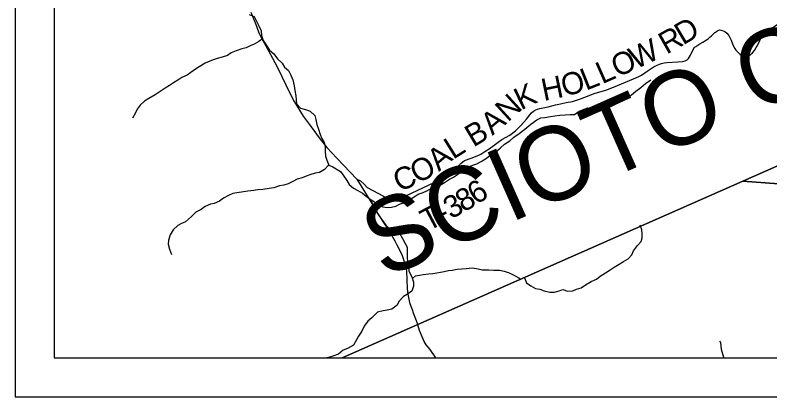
# Model space of a CAD drawing. Extents: x 0 to 44, y -23.8 to 22.
# Drawn here: x 2 to 3.933, y 14 to 14.979 of the extents above; entities that cross this region are included whole.
import ezdxf

# ---------------------------------------------------------------- set-up
doc = ezdxf.new("R2010")
doc.units = 0
for name, color, linetype in [('Default', 7, 'Continuous'), ('GM_X_County_Road', 7, 'Continuous'), ('GM_X_County_Text', 7, 'Continuous'), ('GM_X_Minor_River', 7, 'Continuous'), ('GM_X_Township_Road', 7, 'Continuous'), ('GM_X_Township_Road_Text', 7, 'Continuous'), ('SH_Cut_Line', 7, 'Continuous'), ('SH_Data', 7, 'Continuous')]:
    doc.layers.add(name, color=color, linetype=linetype)

msp = doc.modelspace()

# ---------------------------------------------------------------- linework, layer by layer
at = {"layer": 'Default'}
for points in [[(2.3497, 20.9), (2.1, 20.9), (2.1, 14.1), (2.838, 14.1), (3.0317, 14.1856), (3.8639, 14.5533), (4.3443, 14.7655), (4.4538, 14.8144), (4.856, 14.9939), (4.5387, 15.7097), (4.3476, 16.1408), (4.1422, 16.6361), (4.026, 16.9163), (3.7907, 17.4383), (3.763, 17.5087), (3.455, 18.29), (3.1789, 18.9421), (3.1321, 19.0527), (3.0496, 19.2474), (3.0092, 19.3427), (2.8013, 19.8369), (2.472, 20.6113)], [(2.838, 14.1), (7.2659, 14.1), (7.2787, 14.3616), (7.2065, 14.3659), (6.267, 14.4223), (4.4919, 14.5227), (4.3437, 14.5311), (4.2071, 14.5278), (3.8639, 14.5533), (3.0317, 14.1856)]]:
    msp.add_lwpolyline(points, close=True, dxfattribs=at)
msp.add_lwpolyline([(4.1422, 16.6361), (4.3476, 16.1408), (4.5387, 15.7097), (4.856, 14.9939), (4.4538, 14.8144), (4.3443, 14.7655), (3.8639, 14.5533), (4.2071, 14.5278), (4.3437, 14.5311), (4.4919, 14.5227), (6.267, 14.4223), (7.2065, 14.3659), (7.2787, 14.3616), (7.5613, 14.343)], dxfattribs=at)
at = {"layer": 'GM_X_County_Road'}
for points in [[(2.6042, 14.9868), (2.6157, 14.9579), (2.6238, 14.9364), (2.6307, 14.9214), (2.6424, 14.9001), (2.6717, 14.8463), (2.683, 14.8214), (2.7036, 14.7786), (2.7152, 14.7578), (2.738, 14.72), (2.7558, 14.6961), (2.7813, 14.6611), (2.7987, 14.6393), (2.8239, 14.612), (2.8751, 14.5584), (2.9086, 14.5045), (2.9313, 14.4671), (2.9596, 14.4222), (2.9725, 14.4), (2.9782, 14.3901), (2.9872, 14.3721), (2.9917, 14.3624), (2.9949, 14.3523), (2.9978, 14.3432), (3.0006, 14.3327), (3.0022, 14.3225), (3.0046, 14.2781), (3.0064, 14.2639), (3.0085, 14.2506), (3.0107, 14.2423), (3.0139, 14.2324), (3.0168, 14.2245), (3.02, 14.216), (3.032, 14.1851)], [(3.0774, 14.1), (3.0635, 14.1218), (3.0528, 14.1338), (3.0476, 14.142), (3.0429, 14.1537), (3.0361, 14.17), (3.032, 14.1851)]]:
    msp.add_lwpolyline(points, dxfattribs=at)
at = {"layer": 'GM_X_Minor_River'}
for points in [[(2.5996, 14.981), (2.612, 14.9756), (2.6191, 14.9623), (2.624, 14.952), (2.63, 14.9391), (2.631, 14.9273), (2.6355, 14.914), (2.6422, 14.9037), (2.6516, 14.8896), (2.6632, 14.8797), (2.6722, 14.8667), (2.6839, 14.8561), (2.6903, 14.8458), (2.7004, 14.837), (2.7064, 14.8256), (2.7112, 14.8134), (2.7149, 14.7982), (2.7167, 14.7861), (2.7189, 14.7724), (2.72, 14.7618), (2.7211, 14.7515), (2.7312, 14.7408), (2.744, 14.7374), (2.7557, 14.7327), (2.7674, 14.7217), (2.7707, 14.7114), (2.7733, 14.6989), (2.777, 14.6863), (2.7818, 14.6734), (2.7859, 14.6628), (2.7916, 14.6529), (2.7945, 14.6403), (2.7944, 14.6305), (2.7951, 14.6172), (2.7985, 14.6073), (2.804, 14.594), (2.8139, 14.5898), (2.8334, 14.5783), (2.8402, 14.5687), (2.8496, 14.5554), (2.8559, 14.5451), (2.8668, 14.5352), (2.8781, 14.5291), (2.8902, 14.5222), (2.9034, 14.5111), (2.9166, 14.503), (2.9282, 14.495), (2.9422, 14.4873), (2.9543, 14.4854), (2.9641, 14.4865), (2.9751, 14.489), (2.9846, 14.4943), (2.9971, 14.4988), (3.0092, 14.5055), (3.0225, 14.5134), (3.0324, 14.5198), (3.0449, 14.5243)], [(2.6341, 14.9181), (2.6245, 14.9118), (2.612, 14.905), (2.6025, 14.9005), (2.5915, 14.8957), (2.5805, 14.8927), (2.5665, 14.8875), (2.5536, 14.8823), (2.5441, 14.8759), (2.5301, 14.8714), (2.5176, 14.8677), (2.5073, 14.8643), (2.4967, 14.8602), (2.4865, 14.8561), (2.4717, 14.8463), (2.4622, 14.8407), (2.45, 14.8317), (2.4405, 14.8249), (2.4269, 14.8193), (2.417, 14.8121), (2.4056, 14.8058), (2.3958, 14.7986), (2.384, 14.7915), (2.3718, 14.7832), (2.3586, 14.7746), (2.3426, 14.7652), (2.3312, 14.7584), (2.3202, 14.7482), (2.3126, 14.7384), (2.308, 14.7282), (2.3011, 14.715)], [(3.0449, 14.5243), (3.0544, 14.5288), (3.0642, 14.5333), (3.0741, 14.5374), (3.0873, 14.5426), (3.1002, 14.5497), (3.1124, 14.5584), (3.1226, 14.564), (3.1329, 14.5708), (3.1428, 14.5779), (3.1606, 14.5896), (3.1724, 14.5941), (3.183, 14.5982), (3.194, 14.6038), (3.2073, 14.6124), (3.2172, 14.6203), (3.2304, 14.6278), (3.2434, 14.6388), (3.2536, 14.6478), (3.2669, 14.6568), (3.2779, 14.6662), (3.2912, 14.6753), (3.306, 14.6869), (3.3209, 14.6997), (3.3368, 14.7103), (3.3463, 14.7155), (3.3573, 14.717), (3.3713, 14.7195), (3.3823, 14.721), (3.3951, 14.7228), (3.4088, 14.7235), (3.4216, 14.7242), (3.433, 14.7245), (3.4451, 14.7331), (3.4573, 14.7384), (3.4667, 14.7413), (3.4796, 14.7394), (3.4951, 14.737), (3.5049, 14.74), (3.5159, 14.7429), (3.5257, 14.7452), (3.536, 14.75), (3.5477, 14.7553), (3.5602, 14.7609), (3.5697, 14.7665), (3.5792, 14.7744), (3.5899, 14.7842), (3.6032, 14.7936), (3.615, 14.8038), (3.6283, 14.8136)], [(2.8035, 14.5954), (2.7926, 14.5834), (2.7801, 14.5759), (2.7684, 14.5741), (2.7551, 14.57), (2.7453, 14.5663), (2.7354, 14.5622), (2.7229, 14.5581), (2.7115, 14.5528), (2.6994, 14.5465), (2.6884, 14.5427), (2.677, 14.5417), (2.663, 14.5361), (2.6505, 14.5346), (2.6343, 14.5317), (2.6221, 14.531), (2.6119, 14.5295), (2.596, 14.5273), (2.5801, 14.5248), (2.5684, 14.5237), (2.5574, 14.5219), (2.5464, 14.5166), (2.5335, 14.5095), (2.5233, 14.502), (2.51, 14.4964), (2.5002, 14.4942), (2.4865, 14.4886), (2.4763, 14.481), (2.463, 14.4735), (2.4516, 14.4626), (2.4363, 14.4494), (2.4265, 14.4445), (2.417, 14.4393), (2.4052, 14.4287), (2.3976, 14.4159), (2.3926, 14.4019), (2.3921, 14.392), (2.3951, 14.3787), (2.401, 14.365)], [(2.9104, 14.5068), (2.9135, 14.4985), (2.918, 14.4882), (2.9228, 14.4784), (2.9318, 14.465), (2.9498, 14.4406), (2.9607, 14.4296), (2.9724, 14.4276), (2.9849, 14.4199), (2.9923, 14.4059), (2.9995, 14.3937), (3.0039, 14.3838), (3.0042, 14.3705), (3.0042, 14.358), (3.0052, 14.3462), (3.0074, 14.3364), (3.0089, 14.3227), (3.0163, 14.3079), (3.0204, 14.2946), (3.0203, 14.2843), (3.0161, 14.2714), (3.0051, 14.2635), (2.9952, 14.2579), (2.983, 14.2451), (2.9784, 14.2353), (2.9648, 14.2247), (2.9534, 14.2225), (2.9432, 14.2207), (2.928, 14.2173), (2.9136, 14.203), (2.9033, 14.1947), (2.8945, 14.1815), (2.888, 14.169), (2.88, 14.1562), (2.8743, 14.146), (2.867, 14.1331), (2.8518, 14.1241), (2.8408, 14.12), (2.8283, 14.1094), (2.8139, 14.1046), (2.8006, 14.1005), (2.7988, 14.1)], [(3.3048, 14.3054), (3.3103, 14.2926), (3.3212, 14.2846), (3.3333, 14.2781), (3.3439, 14.2761), (3.3552, 14.2719), (3.37, 14.2684), (3.3821, 14.2687), (3.3938, 14.2721), (3.4033, 14.2754), (3.415, 14.2716), (3.4286, 14.2719), (3.4381, 14.276), (3.4502, 14.2801), (3.4608, 14.2877), (3.476, 14.2959), (3.4893, 14.3019), (3.4991, 14.3099), (3.512, 14.3185), (3.5219, 14.3242), (3.5344, 14.3332), (3.5477, 14.3403), (3.5583, 14.3475), (3.5705, 14.3539), (3.5796, 14.3648), (3.5838, 14.3747), (3.5941, 14.3887), (3.604, 14.3985), (3.6059, 14.4079), (3.6064, 14.4178), (3.6057, 14.4284), (3.6008, 14.4402)], [(3.0176, 14.3036), (3.0254, 14.3105), (3.0356, 14.3123), (3.0455, 14.3141), (3.0599, 14.3156), (3.0697, 14.3163), (3.0799, 14.3181), (3.0988, 14.3218), (3.1102, 14.3244), (3.12, 14.3251), (3.1322, 14.3273), (3.1443, 14.3287), (3.1552, 14.329), (3.1704, 14.3308), (3.1866, 14.3285), (3.1968, 14.3261), (3.2135, 14.326), (3.2267, 14.3252), (3.241, 14.3247), (3.2531, 14.3227), (3.2652, 14.3181), (3.2807, 14.3108), (3.2905, 14.3051), (3.2952, 14.3012)], [(3.816, 14.1), (3.8152, 14.1015), (3.8096, 14.122), (3.8078, 14.1399), (3.8056, 14.1426)]]:
    msp.add_lwpolyline(points, dxfattribs=at)
at = {"layer": 'GM_X_Township_Road'}
msp.add_lwpolyline([(2.8751, 14.5584), (2.885, 14.5542), (2.8946, 14.5447), (2.9022, 14.5372), (2.9165, 14.5291), (2.9434, 14.5146), (2.9488, 14.5111), (2.9543, 14.5083), (2.9587, 14.5065), (2.9622, 14.5053), (2.9668, 14.5037), (2.9713, 14.5039), (2.9765, 14.5049), (3.0029, 14.5168), (3.0734, 14.55), (3.1118, 14.5716), (3.1229, 14.5803), (3.1415, 14.5983), (3.1465, 14.6033), (3.1512, 14.6066), (3.1682, 14.612), (3.1835, 14.6181), (3.1932, 14.6225), (3.2035, 14.629), (3.2143, 14.6359), (3.227, 14.6454), (3.2373, 14.6532), (3.2466, 14.6599), (3.267, 14.6714), (3.2818, 14.6826), (3.2898, 14.6898), (3.2953, 14.6959), (3.3101, 14.7125), (3.3184, 14.7234), (3.3232, 14.7284), (3.3279, 14.7325), (3.3309, 14.7347), (3.3339, 14.7363), (3.3378, 14.7381), (3.3442, 14.7398), (3.3525, 14.7418), (3.3659, 14.7442), (3.3747, 14.7464), (3.3845, 14.7489), (3.397, 14.7517), (3.4119, 14.7547), (3.4279, 14.758), (3.4479, 14.7646), (3.4857, 14.7786), (3.513, 14.7867), (3.5332, 14.7941), (3.584, 14.8154), (3.5979, 14.822), (3.6046, 14.8253), (3.6131, 14.8313), (3.6218, 14.837), (3.629, 14.8426), (3.6371, 14.8473), (3.6426, 14.8501), (3.6505, 14.853), (3.6559, 14.8548), (3.6628, 14.8568), (3.6697, 14.8576), (3.6974, 14.859), (3.7095, 14.8606), (3.7168, 14.8621), (3.7212, 14.8647), (3.7247, 14.8679), (3.7299, 14.8764), (3.7356, 14.8873), (3.7406, 14.8966), (3.7441, 14.899), (3.7544, 14.9057), (3.762, 14.9098), (3.7714, 14.9157), (3.7754, 14.9185), (3.7794, 14.9223), (3.7841, 14.9263), (3.792, 14.9346), (3.799, 14.9391), (3.8041, 14.9411), (3.8079, 14.9403), (3.8138, 14.9391), (3.8184, 14.9368), (3.8229, 14.9328), (3.8283, 14.9269), (3.8312, 14.9217), (3.8344, 14.9152), (3.8374, 14.9053), (3.8399, 14.8995), (3.8437, 14.8932), (3.8463, 14.8895), (3.8488, 14.8869), (3.8522, 14.8831), (3.8569, 14.878), (3.8625, 14.8748), (3.8674, 14.8724), (3.8732, 14.8724), (3.8787, 14.8747), (3.8829, 14.8772), (3.8886, 14.8825), (3.894, 14.8885), (3.8987, 14.896), (3.9019, 14.9014), (3.9076, 14.9142), (3.9112, 14.9207), (3.9137, 14.9241), (3.9167, 14.9286), (3.9213, 14.9338), (3.9548, 14.9565)], dxfattribs=at)
at = {"layer": 'SH_Cut_Line'}
for points in [[(2.1, 20.9), (2.1, 14.1), (2.838, 14.1), (3.0317, 14.1856), (3.8639, 14.5533), (4.3443, 14.7655), (4.4538, 14.8144), (4.856, 14.9939), (4.5387, 15.7097), (4.3476, 16.1408), (4.1422, 16.6361)], [(4.1422, 16.6361), (4.3476, 16.1408), (4.5387, 15.7097), (4.856, 14.9939), (4.4538, 14.8144), (4.3443, 14.7655), (3.8639, 14.5533), (3.0317, 14.1856), (2.838, 14.1), (8.9, 14.1)]]:
    msp.add_lwpolyline(points, dxfattribs=at)
at = {"layer": 'SH_Data'}
for p, q in [((2, 21), (2, 14)), ((2.1, 20.9), (2.1, 14.1)), ((2.1, 14.1), (8.9, 14.1)), ((2.1, 14.1), (2.1, 14.1)), ((2, 14), (9, 14))]:
    msp.add_line(p, q, dxfattribs=at)

# ---------------------------------------------------------------- texts
at = {"layer": 'GM_X_County_Text'}
msp.add_text('SCIOTO COUNTY', height=0.189394, rotation=23.8999, dxfattribs=at).set_placement((2.9443, 14.3021))
at = {"layer": 'GM_X_Township_Road_Text'}
for s, rotation, p in [('D', 30.7679, (3.7109, 14.9011)), ('R', 29.3165, (3.6688, 14.8774)), ('W', 24.8931, (3.5893, 14.8395)), ('O', 23.8947, (3.5426, 14.8188)), ('L', 23.8218, (3.5037, 14.8016)), ('O', 15.0931, (3.407, 14.7696)), ('L', 21.81, (3.4622, 14.785)), ('H', 11.5811, (3.3543, 14.7587)), ('K', 25.8336, (3.2958, 14.7345)), ('N', 42.4353, (3.2624, 14.7032)), ('A', 40.3896, (3.2227, 14.6693)), ('B', 30.6783, (3.174, 14.6394)), ('L', 32.0358, (3.122, 14.6079)), ('A', 40.3179, (3.0856, 14.5769)), ('O', 28.3673, (3.031, 14.5458)), ('C', 23.8917, (2.984, 14.5248)), ('6', 32.7871, (3.1815, 14.4916)), ('8', 30.0519, (3.1487, 14.4726)), ('3', 28.7022, (3.1167, 14.455)), ('T', 27.8512, (3.0577, 14.4238)), ('-', 28.0516, (3.0955, 14.4437))]:
    msp.add_text(s, height=0.0568, rotation=rotation, dxfattribs=at).set_placement(p)

doc.saveas('drawing.dxf')
